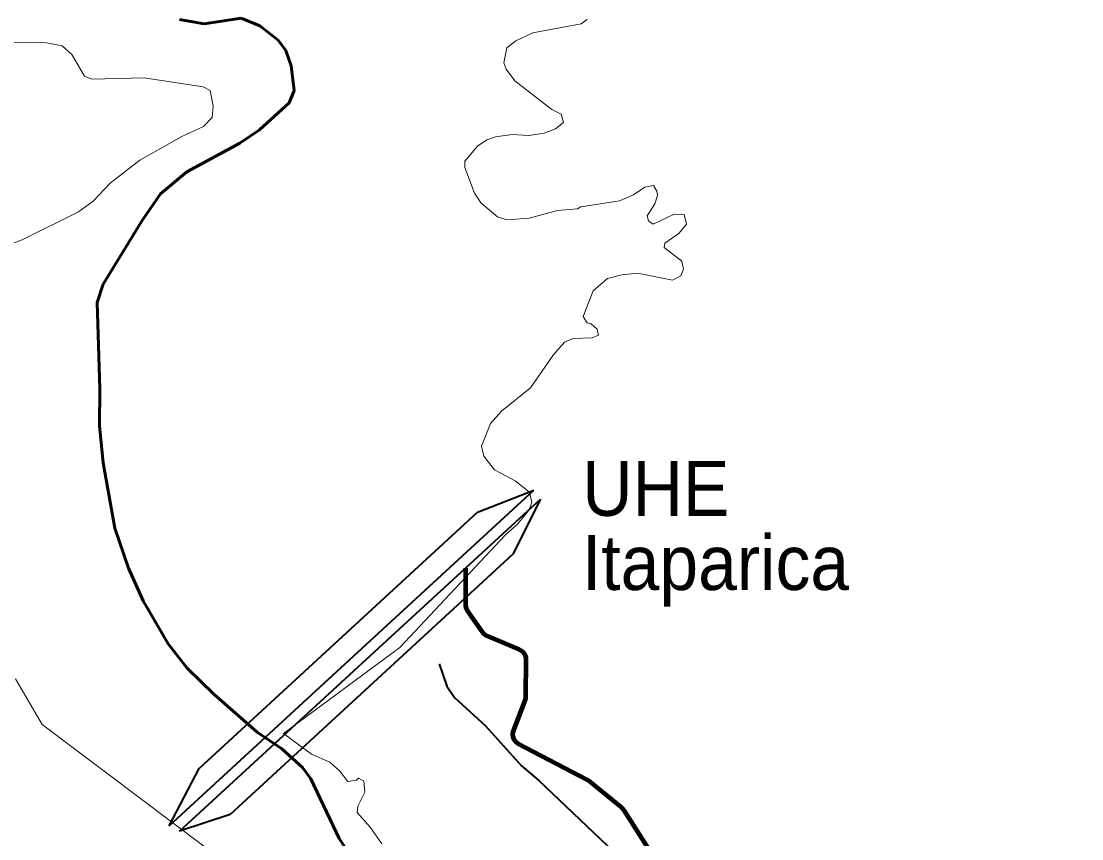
# Model space of a CAD drawing. Extents: x 553962 to 842807, y 8883888 to 9032388.
# Drawn here: x 573949 to 583622, y 8987282 to 8994735 of the extents above; entities that cross this region are included whole.
import ezdxf
from ezdxf.enums import TextEntityAlignment as Align

# ---------------------------------------------------------------- set-up
doc = ezdxf.new("R2010")
doc.units = 0
doc.header["$LTSCALE"] = 160
doc.linetypes.add('DOT_DASHED', pattern=[7.7, 5, -1.2, 0.3, -1.2])
doc.linetypes.add('LONG_DASH_SHORT_DASH', pattern=[9.9, 6, -1.2, 1.5, -1.2])
for name, color, linetype, lineweight in [('15', 7, 'Continuous', 25), ('21', 7, 'Continuous', 25), ('22', 7, 'Continuous', 35), ('34', 7, 'LONG_DASH_SHORT_DASH', 60), ('7', 7, 'Continuous', 90)]:
    doc.layers.add(name, color=color, linetype=linetype, lineweight=lineweight)

msp = doc.modelspace()

# ---------------------------------------------------------------- linework, layer by layer
at = {"layer": '15', "lineweight": 40}
msp.add_lwpolyline([(577759.9, 8988875.8), (577832.5, 8988674.7), (577901.5, 8988571.1), (578184.7, 8988310.3), (578513.4, 8987946.2), (578671.2, 8987814.3), (579419.2, 8987100.9), (579808.1, 8986794.1), (580283, 8986357.3), (580496.3, 8986108), (581364.8, 8985224.5), (581561.3, 8985062.5), (582162.5, 8984452.7), (582384.7, 8984161.9), (582616.4, 8983918.8), (582880.2, 8983596.7), (583472.4, 8982628.4), (583582.5, 8982317.7), (583621.7, 8982083.2), (583591.6, 8981897.8), (583552.5, 8981370), (583461.7, 8980518.1), (583461.7, 8980001.2)], dxfattribs=at)
at = {"layer": '21', "lineweight": 13}
msp.add_line((574141.1, 8988323.6), (575614.7, 8987214.2), dxfattribs=at)
for points in [[(578169.7, 8990769.5), (578148.2, 8990860.4), (578228.1, 8991067.7), (578329.5, 8991180), (578595.4, 8991394.1), (578801.1, 8991690.5), (578904.7, 8991809.2), (578982.8, 8991841.6), (579155.2, 8991848.1), (579213.7, 8991874.2), (579201.1, 8991927.8), (579146.8, 8991975.6), (579112.1, 8991984.6), (579075.6, 8992042.7), (579166.3, 8992278.3), (579295.8, 8992388.4), (579427.6, 8992423.1), (579570.5, 8992438.3), (579888.8, 8992373.7), (579965.9, 8992414.4), (579989.8, 8992474.5), (579975.3, 8992547.4), (579813.6, 8992672.6), (579818.5, 8992711.8), (579946.6, 8992799.3), (580015.8, 8992883.9), (579996.4, 8992972), (579903.2, 8992976.5), (579711.6, 8992886), (579670, 8992916.1), (579657.1, 8992961.4), (579728.3, 8993069.6), (579752, 8993147.2), (579747.7, 8993186.3), (579714.6, 8993238.2), (579635.4, 8993223), (579533.5, 8993151.6), (579406, 8993097.6), (579053.2, 8993043), (579021.4, 8993026.3), (578840, 8993009.1), (578582.4, 8992940.3), (578379.1, 8992925.9), (578292.9, 8992950.7), (578143.9, 8993075.8), (578083.2, 8993169), (577995.1, 8993400.6), (577994.6, 8993460.8), (578109.2, 8993594.8), (578195.8, 8993653.3), (578273.4, 8993681.3), (578427.8, 8993703), (578578, 8993693.5), (578718.8, 8993716), (578822.5, 8993752.7), (578893.8, 8993811.3), (578874.4, 8993888.2), (578790.1, 8993930), (578451.3, 8994193.1), (578370.9, 8994297.2), (578351.4, 8994355.6), (578379.6, 8994492.1), (578461.3, 8994556.7), (578615, 8994628.2), (579056.6, 8994710.7), (579110.2, 8994751.7)], [(573798.6, 8994543.9), (574179, 8994537.4), (574321.5, 8994509.3), (574410.9, 8994430.6), (574526.9, 8994235), (574593.8, 8994206.8), (575069.7, 8994217.5), (575607.7, 8994137.4), (575672.8, 8994102.6), (575700.9, 8993960), (575690, 8993856.5), (575611.7, 8993776), (575415.4, 8993683.4), (575030.8, 8993467.3), (574760.4, 8993259.6), (574604.9, 8993095.5)], [(574604.9, 8993095.5), (574470.8, 8992998.2), (573958.5, 8992743.1), (573612.4, 8992613.3)], [(576341.8, 8988242.2), (577401.4, 8989026.3), (578366.9, 8990052.1), (578479, 8990153.5), (578582.5, 8990281.2), (578606.3, 8990350.1), (578584.9, 8990440.7), (578455, 8990544.6), (578265.4, 8990645.8), (578169.7, 8990769.5), (578169.7, 8990769.5)], [(573896.5, 8988741.1), (574141.1, 8988323.6)], [(577239.2, 8987236.6), (577133.1, 8987389.3), (577014.1, 8987521.3), (577020.2, 8987578.1), (577081.9, 8987708.2), (577075.4, 8987808.1), (577026.8, 8987833.3), (577007.3, 8987816.6), (576929.1, 8987803.9), (576854.5, 8987899.6), (576763.6, 8987982), (576595.8, 8988054.3), (576341.8, 8988242.2)]]:
    msp.add_lwpolyline(points, dxfattribs=at)
at = {"layer": '22'}
for p, q in [((575299.1, 8987399.3), (578625.8, 8990461.6)), ((578111.1, 8990259.6), (578625.8, 8990461.6)), ((575393.3, 8987350.1), (578684.3, 8990379.5)), ((578684.3, 8990379.5), (578432.5, 8989875.9)), ((575573.4, 8987923.7), (578111.1, 8990259.6)), ((575853.7, 8987502), (578432.5, 8989875.9)), ((575299.1, 8987399.3), (575573.4, 8987923.7)), ((575853.7, 8987502), (575393.3, 8987350.1))]:
    msp.add_line(p, q, dxfattribs=at)
at = {"layer": '34'}
msp.add_lwpolyline([(575394, 8994749.3), (575618.8, 8994712.5), (575955.7, 8994764.3), (576124.6, 8994693), (576292.4, 8994562), (576364.1, 8994468.9), (576412.1, 8994327.7), (576440.1, 8994102.6), (576392.7, 8993990.5), (576122.7, 8993744.2), (575943, 8993623), (575458.6, 8993363.4), (575221, 8993160.3), (575052.4, 8992918.2), (574695.8, 8992339.1), (574641.7, 8992170), (574667.6, 8991383.4), (574663.3, 8991045.9), (574695.7, 8990709.2), (574803.7, 8990112.5), (574929.2, 8989749.1), (575061.1, 8989450.8), (575289.9, 8989059.8), (575463.1, 8988836.8), (575705.1, 8988599.2), (576100.8, 8988253.1), (576327, 8988102.8), (576516, 8987931.2), (576589.4, 8987829.4), (576848.8, 8987284.7), (577014.7, 8987034.6)], dxfattribs=at)
at = {"layer": '7'}
msp.add_lwpolyline([(578000, 8989750), (577999.8, 8989421.2), (578001.8, 8989401.3), (578007.7, 8989382.3), (578017.3, 8989364.7), (578017.6, 8989364.3), (578153.8, 8989167.2), (578166.7, 8989152), (578182.5, 8989139.7), (578197.3, 8989131.9), (578491.1, 8989008.4), (578508.6, 8988998.8), (578523.9, 8988986), (578536.4, 8988970.3), (578545.5, 8988952.6), (578550.8, 8988933.3), (578552.3, 8988915.2), (578549.2, 8988582.4), (578547, 8988561.5), (578541.9, 8988543.7), (578437.7, 8988272.2), (578432.4, 8988252.9), (578431.1, 8988233), (578433.8, 8988213.2), (578440.3, 8988194.3), (578450.5, 8988177.1), (578463.8, 8988162.3), (578479.9, 8988150.4), (578484.8, 8988147.7), (579106.3, 8987823.8), (579130, 8987809.2), (579139.5, 8987801.9), (579418.1, 8987573.9), (579434, 8987558.4), (579444.3, 8987544.4), (579715.2, 8987116.9)], dxfattribs=at)
at = {"layer": '7', "linetype": 'DOT_DASHED'}
msp.add_lwpolyline([(578000, 8989750), (577999.8, 8989421.2), (578001.8, 8989401.3), (578007.7, 8989382.3), (578017.3, 8989364.7), (578017.6, 8989364.3), (578153.8, 8989167.2), (578166.7, 8989152), (578182.5, 8989139.7), (578197.3, 8989131.9), (578491.1, 8989008.4), (578508.6, 8988998.8), (578523.9, 8988986), (578536.4, 8988970.3), (578545.5, 8988952.6), (578550.8, 8988933.3), (578552.3, 8988915.2), (578549.2, 8988582.4), (578547, 8988561.5), (578541.9, 8988543.7), (578437.7, 8988272.2), (578432.4, 8988252.9), (578431.1, 8988233), (578433.8, 8988213.2), (578440.3, 8988194.3), (578450.5, 8988177.1), (578463.8, 8988162.3), (578479.9, 8988150.4), (578484.8, 8988147.7), (579106.3, 8987823.8), (579130, 8987809.2), (579139.5, 8987801.9), (579418.1, 8987573.9), (579434, 8987558.4), (579444.3, 8987544.4), (579715.2, 8987116.9)], dxfattribs=at)

# ---------------------------------------------------------------- texts
at = {"layer": '22', "width": 0.95}
for s, p in [('UHE', (579736.7, 8990226.1)), ('Itaparica', (580281.3, 8989550))]:
    msp.add_text(s, height=500, dxfattribs=at).set_placement(p, align=Align.CENTER)

doc.saveas('drawing.dxf')
